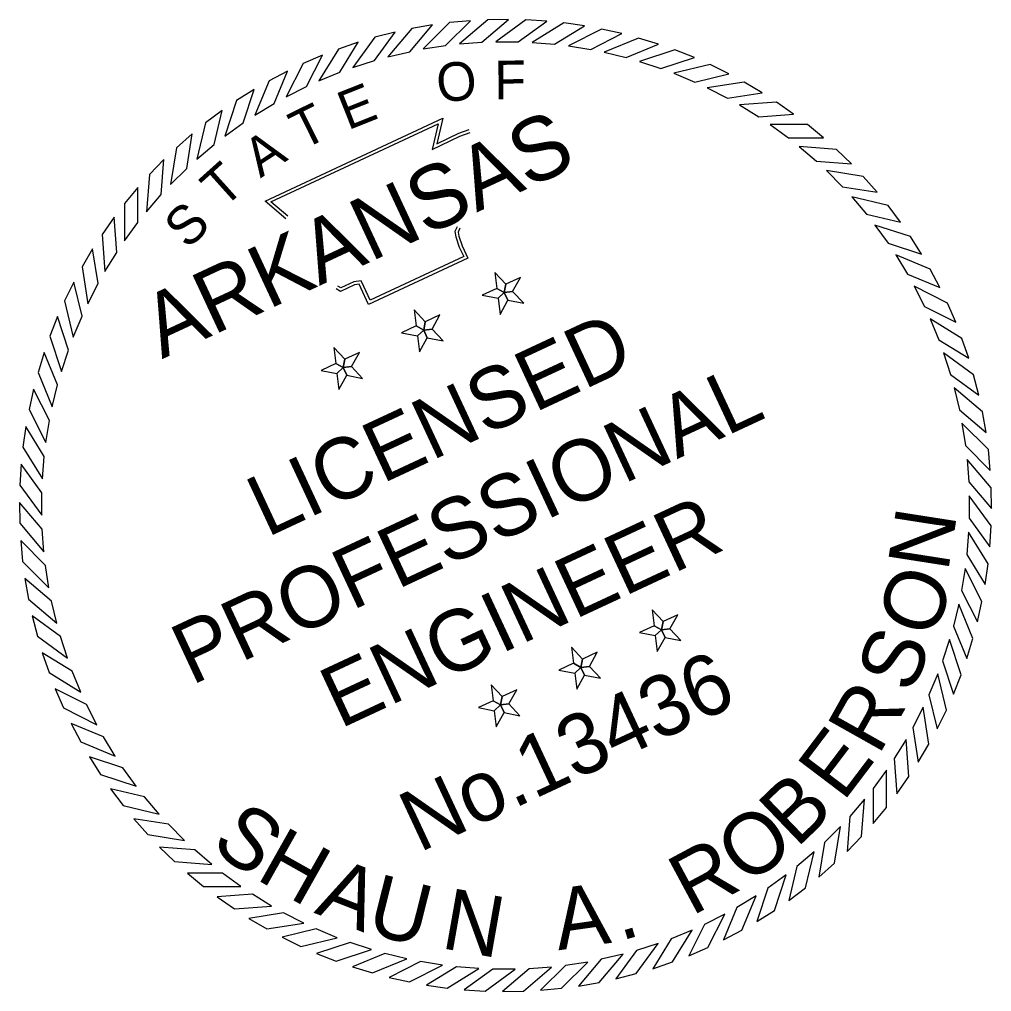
# Model space of a CAD drawing. Extents: x 756658 to 763719, y 1656413 to 1661090.
# Drawn here: x 763474.8 to 763713.5, y 1660851.4 to 1661090 of the extents above; entities that cross this region are included whole.
import ezdxf

# ---------------------------------------------------------------- set-up
doc = ezdxf.new("R2010")
doc.units = 0
doc.layers.add('G-ANNO-SYMB', color=7, linetype='Continuous')

msp = doc.modelspace()

# ---------------------------------------------------------------- linework, layer by layer
at = {"layer": 'G-ANNO-SYMB'}
for points in [[(763576.23, 1661088.65), (763571.18, 1661087.77), (763565.24, 1661080.82), (763570.63, 1661082.09)], [(763585.54, 1661089.69), (763580.43, 1661089.21), (763573.97, 1661082.75), (763579.44, 1661083.59)], [(763594.91, 1661090), (763589.78, 1661089.92), (763582.82, 1661083.98), (763588.35, 1661084.4)], [(763604.27, 1661089.57), (763599.14, 1661089.9), (763591.75, 1661084.52), (763597.29, 1661084.51)], [(763613.56, 1661088.41), (763608.48, 1661089.14), (763600.68, 1661084.36), (763606.21, 1661083.91)], [(763567.03, 1661086.88), (763562.06, 1661085.61), (763556.69, 1661078.21), (763561.96, 1661079.9)], [(763622.74, 1661086.53), (763617.73, 1661087.65), (763609.58, 1661083.5), (763615.06, 1661082.61)], [(763558, 1661084.39), (763553.14, 1661082.73), (763548.36, 1661074.94), (763553.49, 1661077.04)], [(763631.74, 1661083.93), (763626.84, 1661085.44), (763618.39, 1661081.94), (763623.77, 1661080.63)], [(763549.19, 1661081.21), (763544.48, 1661079.17), (763540.33, 1661071.02), (763545.27, 1661073.52)], [(763640.51, 1661080.63), (763635.74, 1661082.52), (763627.04, 1661079.69), (763632.31, 1661077.96)], [(763648.99, 1661076.65), (763644.39, 1661078.91), (763635.49, 1661076.78), (763640.61, 1661074.64)], [(763540.66, 1661077.34), (763536.12, 1661074.94), (763532.62, 1661066.49), (763537.36, 1661069.37)], [(763657.14, 1661072.02), (763652.72, 1661074.64), (763643.69, 1661073.21), (763648.62, 1661070.68)], [(763532.45, 1661072.81), (763528.12, 1661070.07), (763525.29, 1661061.37), (763529.79, 1661064.61)], [(763664.89, 1661066.77), (763660.7, 1661069.72), (763651.58, 1661069), (763656.3, 1661066.09)], [(763524.63, 1661067.66), (763520.52, 1661064.58), (763518.39, 1661055.69), (763522.62, 1661059.27)], [(763517.24, 1661061.9), (763513.38, 1661058.51), (763511.95, 1661049.48), (763515.89, 1661053.39)], [(763672.22, 1661060.92), (763668.26, 1661064.2), (763659.12, 1661064.2), (763663.59, 1661060.92)], [(763679.05, 1661054.52), (763675.37, 1661058.09), (763666.25, 1661058.81), (763670.46, 1661055.2)], [(763510.32, 1661055.59), (763506.74, 1661051.9), (763506.03, 1661042.79), (763509.64, 1661046.99)], [(763685.37, 1661047.6), (763681.98, 1661051.45), (763672.95, 1661052.88), (763676.85, 1661048.95)], [(763503.91, 1661048.75), (763500.64, 1661044.8), (763500.64, 1661035.65), (763503.91, 1661040.12)], [(763691.12, 1661040.21), (763688.05, 1661044.31), (763679.15, 1661046.45), (763682.74, 1661042.22)], [(763498.07, 1661041.43), (763495.11, 1661037.23), (763495.83, 1661028.11), (763498.74, 1661032.83)], [(763696.28, 1661032.38), (763693.53, 1661036.72), (763684.84, 1661039.54), (763688.08, 1661035.05)], [(763492.81, 1661033.67), (763490.2, 1661029.25), (763491.63, 1661020.22), (763494.16, 1661025.15)], [(763700.81, 1661024.18), (763698.41, 1661028.72), (763689.96, 1661032.22), (763692.84, 1661027.48)], [(763593.85, 1661022.97), (763594.24, 1661025.01), (763591.54, 1661027.91), (763592.02, 1661023.98)], [(763593.85, 1661022.97), (763595.91, 1661023.22), (763597.84, 1661026.69), (763594.24, 1661025.01)], [(763488.18, 1661025.52), (763485.92, 1661020.92), (763488.06, 1661012.03), (763490.2, 1661017.14)], [(763593.85, 1661022.97), (763592.02, 1661023.98), (763588.43, 1661022.3), (763592.32, 1661021.55)], [(763704.67, 1661015.65), (763702.64, 1661020.36), (763694.49, 1661024.51), (763696.99, 1661019.56)], [(763593.85, 1661022.97), (763592.32, 1661021.55), (763592.81, 1661017.61), (763594.73, 1661021.08)], [(763593.85, 1661022.97), (763594.73, 1661021.08), (763598.62, 1661020.32), (763595.91, 1661023.22)], [(763484.21, 1661017.04), (763482.31, 1661012.27), (763485.14, 1661003.57), (763486.87, 1661008.84)], [(763574.07, 1661013.75), (763574.47, 1661015.79), (763571.77, 1661018.69), (763572.25, 1661014.76)], [(763574.07, 1661013.75), (763576.14, 1661014), (763578.06, 1661017.47), (763574.47, 1661015.79)], [(763574.07, 1661013.75), (763572.25, 1661014.76), (763568.66, 1661013.08), (763572.55, 1661012.32)], [(763707.86, 1661006.84), (763706.2, 1661011.69), (763698.4, 1661016.47), (763700.51, 1661011.34)], [(763574.07, 1661013.75), (763572.55, 1661012.32), (763573.03, 1661008.39), (763574.95, 1661011.86)], [(763574.07, 1661013.75), (763574.95, 1661011.86), (763578.84, 1661011.1), (763576.14, 1661014)], [(763554.3, 1661004.52), (763554.7, 1661006.57), (763551.99, 1661009.47), (763552.48, 1661005.53)], [(763480.91, 1661008.27), (763479.4, 1661003.37), (763482.9, 1660994.92), (763484.21, 1661000.31)], [(763554.3, 1661004.52), (763556.37, 1661004.78), (763558.29, 1661008.24), (763554.7, 1661006.57)], [(763710.35, 1660997.8), (763709.07, 1661002.78), (763701.68, 1661008.15), (763703.37, 1661002.87)], [(763554.3, 1661004.52), (763552.48, 1661005.53), (763548.88, 1661003.86), (763552.77, 1661003.1)], [(763554.3, 1661004.52), (763555.18, 1661002.64), (763559.07, 1661001.88), (763556.37, 1661004.78)], [(763554.3, 1661004.52), (763552.77, 1661003.1), (763553.26, 1660999.17), (763555.18, 1661002.64)], [(763478.31, 1660999.27), (763477.19, 1660994.26), (763481.34, 1660986.12), (763482.22, 1660991.59)], [(763712.12, 1660988.6), (763711.24, 1660993.66), (763704.28, 1660999.6), (763705.56, 1660994.2)], [(763713.16, 1660979.29), (763712.68, 1660984.4), (763706.21, 1660990.87), (763707.06, 1660985.39)], [(763476.42, 1660990.09), (763475.7, 1660985.02), (763480.47, 1660977.22), (763480.93, 1660982.74)], [(763475.26, 1660980.8), (763474.94, 1660975.68), (763480.31, 1660968.28), (763480.33, 1660973.82)], [(763713.47, 1660969.93), (763713.39, 1660975.06), (763707.45, 1660982.01), (763707.87, 1660976.49)], [(763474.84, 1660971.44), (763474.91, 1660966.31), (763480.85, 1660959.35), (763480.44, 1660964.88)], [(763713.04, 1660960.57), (763713.37, 1660965.69), (763707.99, 1660973.09), (763707.97, 1660967.55)], [(763711.88, 1660951.27), (763712.61, 1660956.35), (763707.83, 1660964.15), (763707.38, 1660958.63)], [(763475.14, 1660962.07), (763475.62, 1660956.97), (763482.09, 1660950.5), (763481.24, 1660955.98)], [(763710, 1660942.1), (763711.12, 1660947.1), (763706.97, 1660955.25), (763706.08, 1660949.78)], [(763476.19, 1660952.76), (763477.07, 1660947.71), (763484.02, 1660941.77), (763482.74, 1660947.16)], [(763632.46, 1660940.16), (763632.86, 1660942.21), (763630.15, 1660945.11), (763630.64, 1660941.17)], [(763707.4, 1660933.1), (763708.91, 1660938), (763705.41, 1660946.45), (763704.1, 1660941.06)], [(763477.96, 1660943.56), (763479.23, 1660938.59), (763486.63, 1660933.22), (763484.93, 1660938.5)], [(763632.46, 1660940.16), (763634.53, 1660940.42), (763636.45, 1660943.88), (763632.86, 1660942.21)], [(763632.46, 1660940.16), (763630.64, 1660941.17), (763627.04, 1660939.5), (763630.93, 1660938.74)], [(763632.46, 1660940.16), (763633.34, 1660938.27), (763637.23, 1660937.52), (763634.53, 1660940.42)], [(763632.46, 1660940.16), (763630.93, 1660938.74), (763631.42, 1660934.81), (763633.34, 1660938.27)], [(763612.68, 1660930.94), (763613.08, 1660932.99), (763610.38, 1660935.89), (763610.86, 1660931.95)], [(763704.1, 1660924.33), (763705.99, 1660929.1), (763703.16, 1660937.79), (763701.43, 1660932.53)], [(763480.44, 1660934.53), (763482.1, 1660929.68), (763489.9, 1660924.9), (763487.79, 1660930.03)], [(763612.68, 1660930.94), (763614.75, 1660931.2), (763616.67, 1660934.66), (763613.08, 1660932.99)], [(763612.68, 1660930.94), (763610.86, 1660931.95), (763607.27, 1660930.28), (763611.16, 1660929.52)], [(763612.68, 1660930.94), (763611.16, 1660929.52), (763611.64, 1660925.59), (763613.56, 1660929.05)], [(763612.68, 1660930.94), (763613.56, 1660929.05), (763617.45, 1660928.3), (763614.75, 1660931.2)], [(763700.12, 1660915.84), (763702.38, 1660920.45), (763700.25, 1660929.34), (763698.11, 1660924.23)], [(763592.91, 1660921.72), (763593.31, 1660923.77), (763590.6, 1660926.66), (763591.09, 1660922.73)], [(763483.63, 1660925.72), (763485.66, 1660921.01), (763493.81, 1660916.86), (763491.31, 1660921.81)], [(763592.91, 1660921.72), (763594.98, 1660921.97), (763596.9, 1660925.44), (763593.31, 1660923.77)], [(763592.91, 1660921.72), (763591.09, 1660922.73), (763587.5, 1660921.06), (763591.39, 1660920.3)], [(763592.91, 1660921.72), (763591.39, 1660920.3), (763591.87, 1660916.37), (763593.79, 1660919.83)], [(763592.91, 1660921.72), (763593.79, 1660919.83), (763597.68, 1660919.08), (763594.98, 1660921.97)], [(763695.49, 1660907.7), (763698.11, 1660912.11), (763696.68, 1660921.15), (763694.14, 1660916.22)], [(763487.5, 1660917.19), (763489.9, 1660912.65), (763498.35, 1660909.15), (763495.46, 1660913.89)], [(763690.24, 1660899.94), (763693.19, 1660904.14), (763692.47, 1660913.26), (763689.56, 1660908.54)], [(763492.02, 1660908.98), (763494.77, 1660904.65), (763503.47, 1660901.82), (763500.22, 1660906.32)], [(763684.39, 1660892.62), (763687.66, 1660896.57), (763687.66, 1660905.72), (763684.39, 1660901.24)], [(763497.18, 1660901.16), (763500.26, 1660897.06), (763509.15, 1660894.92), (763505.56, 1660899.15)], [(763677.99, 1660885.78), (763681.56, 1660889.46), (763682.28, 1660898.58), (763678.66, 1660894.38)], [(763502.93, 1660893.77), (763506.32, 1660889.92), (763515.36, 1660888.49), (763511.45, 1660892.42)], [(763671.07, 1660879.47), (763674.92, 1660882.86), (763676.35, 1660891.89), (763672.42, 1660887.98)], [(763509.25, 1660886.85), (763512.93, 1660883.28), (763522.05, 1660882.56), (763517.85, 1660886.17)], [(763663.67, 1660873.71), (763667.78, 1660876.79), (763669.91, 1660885.68), (763665.69, 1660882.1)], [(763516.09, 1660880.45), (763520.04, 1660877.17), (763529.19, 1660877.17), (763524.71, 1660880.45)], [(763655.85, 1660868.56), (763660.18, 1660871.3), (763663.01, 1660880), (763658.52, 1660876.76)], [(763523.41, 1660874.6), (763527.61, 1660871.65), (763536.72, 1660872.36), (763532.01, 1660875.28)], [(763647.65, 1660864.03), (763652.18, 1660866.43), (763655.68, 1660874.88), (763650.95, 1660872)], [(763531.17, 1660869.34), (763535.58, 1660866.73), (763544.61, 1660868.16), (763539.68, 1660870.69)], [(763639.12, 1660860.16), (763643.83, 1660862.2), (763647.98, 1660870.35), (763643.03, 1660867.84)], [(763539.31, 1660864.71), (763543.92, 1660862.46), (763552.81, 1660864.59), (763547.7, 1660866.73)], [(763630.31, 1660856.97), (763635.16, 1660858.63), (763639.94, 1660866.43), (763634.81, 1660864.33)], [(763547.79, 1660860.74), (763552.56, 1660858.85), (763561.26, 1660861.67), (763556, 1660863.4)], [(763621.27, 1660854.49), (763626.24, 1660855.76), (763631.62, 1660863.16), (763626.34, 1660861.46)], [(763556.56, 1660857.44), (763561.47, 1660855.93), (763569.92, 1660859.43), (763564.53, 1660860.74)], [(763612.07, 1660852.72), (763617.13, 1660853.6), (763623.07, 1660860.55), (763617.67, 1660859.28)], [(763565.56, 1660854.84), (763570.57, 1660853.72), (763578.72, 1660857.87), (763573.25, 1660858.76)], [(763574.74, 1660852.95), (763579.82, 1660852.23), (763587.62, 1660857.01), (763582.09, 1660857.46)], [(763584.04, 1660851.79), (763589.16, 1660851.47), (763596.56, 1660856.85), (763591.01, 1660856.86)], [(763593.4, 1660851.37), (763598.53, 1660851.45), (763605.48, 1660857.39), (763599.95, 1660856.97)], [(763602.76, 1660851.68), (763607.87, 1660852.16), (763614.34, 1660858.62), (763608.86, 1660857.77)]]:
    msp.add_lwpolyline(points, close=True, dxfattribs=at)
for points in [[(763540.23, 1661041.09), (763535.16, 1661045.38), (763578.77, 1661065.74), (763577.26, 1661059.46), (763580.2, 1661060.88), (763582.66, 1661062.07), (763585.26, 1661062.95)], [(763540.72, 1661041.67), (763536.56, 1661045.19), (763577.66, 1661064.38), (763576.14, 1661058.08), (763580.53, 1661060.2), (763582.95, 1661061.36), (763585.51, 1661062.23)], [(763582.98, 1661038.77), (763582.51, 1661037.82), (763582.69, 1661036.8), (763583.5, 1661034.42), (763584.9, 1661031.41), (763560.55, 1661020.05), (763558.66, 1661024.12), (763558.23, 1661025.03), (763557.11, 1661024.87), (763553.64, 1661023.25), (763552.59, 1661023.91)], [(763582.29, 1661039.1), (763581.72, 1661037.93), (763581.95, 1661036.61), (763582.79, 1661034.14), (763583.89, 1661031.78), (763560.92, 1661021.07), (763559.35, 1661024.45), (763558.69, 1661025.86), (763556.89, 1661025.61), (763553.69, 1661024.12), (763552.99, 1661024.56)]]:
    msp.add_lwpolyline(points, dxfattribs=at)

# ---------------------------------------------------------------- texts
for s, height, rotation, p in [('O', 9.49, 6.2218, (763577.71, 1661069.53)), ('F', 9.49, 0.3628, (763591.43, 1661070.4)), ('E', 9.49, 21.672, (763555.45, 1661062.74)), ('T', 9.49, 26.4789, (763544.31, 1661057.86)), ('ARKANSAS', 15.494, 25, (763509.84, 1661006.58)), ('A', 9.49, 33.6788, (763534, 1661050.97)), ('T', 9.49, 41.9015, (763524.83, 1661043.37)), ('S', 9.49, 44.7726, (763516.18, 1661033.36)), ('LICENSED', 15, 25, (763535.58, 1660962.77)), ('PROFESSIONAL', 15.0001, 25, (763517.05, 1660926.45)), ('ENGINEER', 15, 25, (763553.54, 1660915.79)), ('N', 15, 81.1007, (763702.78, 1660954.18)), ('O', 15, 69.7757, (763699.05, 1660937.54)), ('S', 15, 68.4878, (763693.92, 1660924.16)), ('No.13436', 14.941, 25, (763572.95, 1660885.39)), ('R', 15, 60.6597, (763685.73, 1660909.09)), ('E', 15, 52.8315, (763677.04, 1660897.72)), ('B', 15, 43.885, (763665.6, 1660886.4)), ('S', 15, 323.1636, (763521.39, 1660886.89)), ('O', 15, 36.4296, (763653.32, 1660877.16)), ('H', 15, 330.619, (763532.55, 1660879.12)), ('R', 15, 28.2287, (763639.82, 1660869.8)), ('A', 15, 338.4472, (763546.97, 1660870.74)), ('U', 15, 345.9026, (763559.58, 1660865.83)), ('N', 15, 349.9326, (763578, 1660862.09)), ('A', 15, 8.0991, (763607.14, 1660861.48)), ('.', 15, 16.3, (763622.35, 1660863.75))]:
    msp.add_text(s, height=height, rotation=rotation, dxfattribs=at).set_placement(p)

doc.saveas('drawing.dxf')
